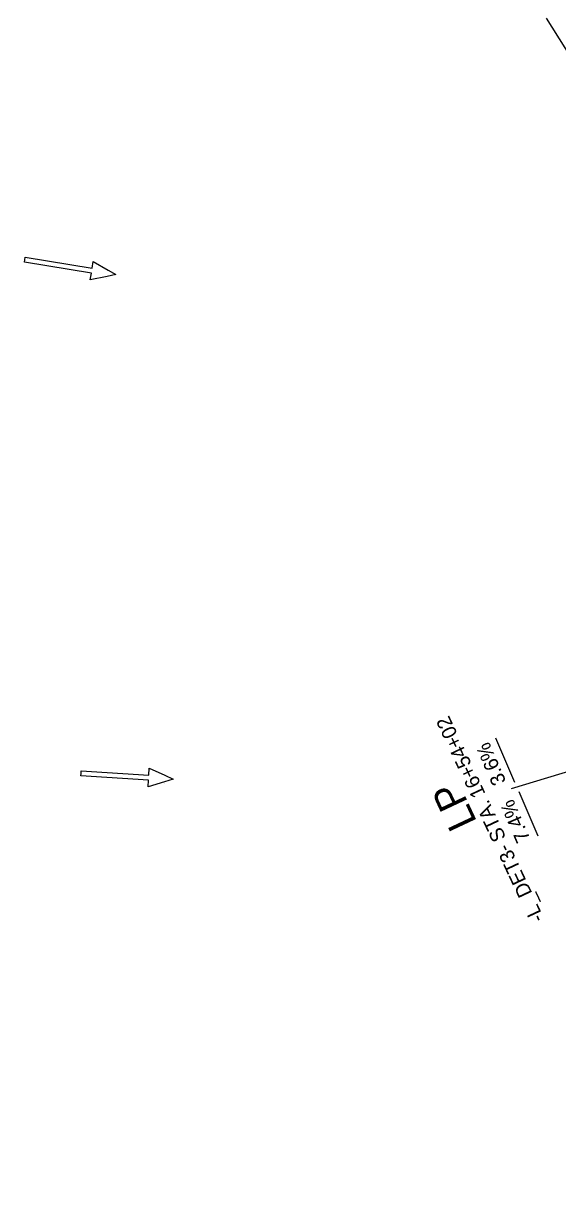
# Model space of a CAD drawing. Extents: x 465700 to 483515, y 488970 to 507540.
# Drawn here: x 477310 to 477587, y 499135 to 499740 of the extents above; entities that cross this region are included whole.
import ezdxf

# ---------------------------------------------------------------- set-up
doc = ezdxf.new("R2010")
doc.units = 0
for name, color, linetype in [('Default', 7, 'Continuous'), ('Exist Plan Preparation Drainage Flow Arrows', 7, 'Continuous'), ('Exist Plan Preparation Watershed Blue', 7, 'Continuous'), ('Prop Plan Preparation Sag', 7, 'Continuous'), ('Prop Plan Preparation Sag Label', 7, 'Continuous')]:
    doc.layers.add(name, color=color, linetype=linetype)

# ---------------------------------------------------------------- blocks, each defined once
blk = doc.blocks.new('Existing ground flow arrow')
at = {"layer": 'Default'}
blk.add_line((2.5, -4.33), (2.5, -4.33), dxfattribs=at)
blk.add_lwpolyline([(-1.29, -47.2), (-1.28, -12.53), (-4.77, -12.53), (-1.65, -4.33), (0, 0), (1.65, -4.33), (4.78, -12.53), (1.28, -12.52), (1.29, -47.19), (0, -47.2)], close=True, dxfattribs=at)

msp = doc.modelspace()

# ---------------------------------------------------------------- linework, layer by layer
at = {"layer": 'Exist Plan Preparation Watershed Blue'}
msp.add_lwpolyline([(477858.24, 499093.41), (477832.51, 499190.03), (477802.27, 499285.34), (477767.58, 499379.12), (477747.49, 499427.65), (477728.52, 499471.17), (477710.77, 499509.04), (477685.16, 499561.27), (477643.08, 499639.33), (477611.01, 499694.79), (477581.24, 499742.27)], dxfattribs=at)
at = {"layer": 'Prop Plan Preparation Sag'}
msp.add_line((477802.3, 499416.88), (477562.92, 499343.47), dxfattribs=at)
at = {"layer": 'Prop Plan Preparation Sag Label'}
for p, q in [((477564.82, 499346.74), (477554.91, 499369.69)), ((477566.8, 499342.15), (477576.71, 499319.2))]:
    msp.add_line(p, q, dxfattribs=at)

# ---------------------------------------------------------------- block references
at = {"layer": 'Exist Plan Preparation Drainage Flow Arrows', "yscale": 1.0124070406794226}
for p, xscale, rotation in [((477358.39, 499609.56), 1.0124070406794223, -99.2265003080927), ((477388.01, 499348.59), 1.012407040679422, -93.45325332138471)]:
    msp.add_blockref('Existing ground flow arrow', p, dxfattribs=dict(at, xscale=xscale, rotation=rotation))

# ---------------------------------------------------------------- texts
at = {"layer": 'Prop Plan Preparation Sag Label'}
for s, height, rotation, p in [('-L_DET3- STA. 16+54+02', 7.5, 115.16206, (477580.13, 499276.37)), ('3.6%', 7.5, 113.35254, (477560.42, 499347.26)), ('LP', 15, 115.16541, (477545.41, 499326.4)), ('7.4%', 7.5, 113.35254, (477572.91, 499317.65))]:
    msp.add_text(s, height=height, rotation=rotation, dxfattribs=at).set_placement(p)

doc.saveas('drawing.dxf')
